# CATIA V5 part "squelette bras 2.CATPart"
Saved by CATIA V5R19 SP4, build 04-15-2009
Part number: squelette bras 2
Bounding box of the stored display mesh (mm): x -600 to -400, y 0 to 100, z 0 to 335.41
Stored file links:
  G:\EU_thinkMotion\CFAO_2010\MMS_groupe1\MMS_groupe1\OK\rragonneau\rragonneau\squelette bras 2.CATPart
  G:\EU_thinkMotion\CFAO_2010\MMS_groupe1\MMS_groupe1\OK\rragonneau\rragonneau\Squelette.CATProduct
  G:\EU_thinkMotion\CFAO_2010\MMS_groupe1\MMS_groupe1\OK\rragonneau\rragonneau\squelette de base.CATPart
  G:\EU_thinkMotion\CFAO_2010\MMS_groupe1\MMS_groupe1\OK\rragonneau\rragonneau\squelette bras 1.CATPart
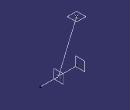
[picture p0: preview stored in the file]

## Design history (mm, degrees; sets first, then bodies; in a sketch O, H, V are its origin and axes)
External parameters (linked from other documents)
  External.epaisseur_pneu = 60 mm
Set1
  Line1: type Normal, RefPoint Point1, RefSkin yz-plane, Start -100, End 100
  Line2: type PtPt, FirstPoint Point2, SecondPoint Point1
  Plane1: type OffsetPt, RefPlane xy-plane, RefPoint Point2
  Plane2: type OffsetPt, RefPlane yz-plane, RefPoint Point1
  Plane3: type Offset, RefPlane Plane2, Offset 120 {= External.epaisseur_pneu *2}, reversed
Set2
  Point1: linked copy from another document
  Point2: linked copy from another document
Body1 (main body)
